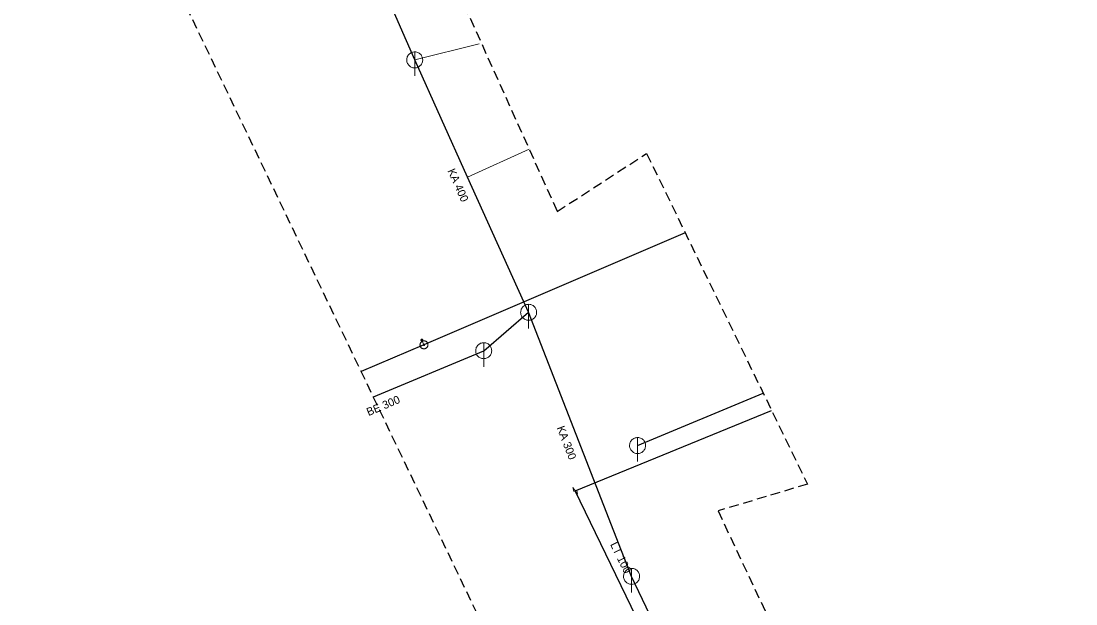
# Model space of a CAD drawing. Extents: x -688691 to -688449, y -974248 to -973966.
# Drawn here: x -688691.4 to -688559.6, y -974177 to -974104.2 of the extents above; entities that cross this region are included whole.
import ezdxf

# ---------------------------------------------------------------- set-up
doc = ezdxf.new("R2010")
doc.units = 0
doc.header["$LTSCALE"] = 0.4
doc.linetypes.add('MEDIUM_DASHED', pattern=[4.5, 3, -1.5])
for name, color, linetype, lineweight in [('1', 7, 'MEDIUM_DASHED', 25), ('11', 7, 'Continuous', 13), ('14', 7, 'Continuous', 25), ('17', 7, 'Continuous', 25), ('22', 7, 'Continuous', 13), ('47', 7, 'Continuous', 13), ('9', 7, 'Continuous', 13)]:
    doc.layers.add(name, color=color, linetype=linetype, lineweight=lineweight)

msp = doc.modelspace()

# ---------------------------------------------------------------- linework, layer by layer
at = {"layer": '1'}
msp.add_lwpolyline([(-688492.642, -974007.422), (-688474.778, -973965.553), (-688449.099, -973975.602), (-688472.545, -974030.309), (-688492.642, -974033.659), (-688555.165, -974021.936), (-688650.066, -974071.061), (-688624.387, -974128.002), (-688613.222, -974120.745), (-688593.125, -974162.055), (-688604.29, -974165.404), (-688581.96, -974212.855), (-688565.213, -974206.156), (-688558.514, -974230.719), (-688607.64, -974248.024), (-688622.154, -974231.277), (-688607.64, -974225.136), (-688626.62, -974194.433), (-688691.376, -974059.338), (-688565.213, -973995.698), (-688544, -974002.397)], close=True, dxfattribs=at)
at = {"layer": '11'}
for p, q in [((-688634.145, -974107.05), (-688642.199, -974109.067)), ((-688627.9, -974120.212), (-688635.58, -974123.722))]:
    msp.add_line(p, q, dxfattribs=at)
at = {"layer": '14'}
for p, q in [((-688642.199, -974109.067), (-688647.127, -974097.744)), ((-688633.579, -974145.386), (-688627.959, -974140.596)), ((-688647.359, -974151.167), (-688633.579, -974145.386)), ((-688614.35, -974157.235), (-688598.649, -974150.701))]:
    msp.add_line(p, q, dxfattribs=at)
at = {"layer": '14', "lineweight": 13}
msp.add_line((-688641.288, -974144.068), (-688641.038, -974144.657), dxfattribs=at)
at = {"layer": '14'}
for points in [[(-688627.959, -974140.596), (-688635.58, -974123.722), (-688642.199, -974109.067)], [(-688600.487, -974203.944), (-688609.114, -974186.109), (-688615.099, -974173.573), (-688627.959, -974140.596)]]:
    msp.add_lwpolyline(points, dxfattribs=at)
at = {"layer": '17'}
for p, q in [((-688608.391, -974130.675), (-688641.038, -974144.657)), ((-688641.038, -974144.657), (-688648.882, -974147.989)), ((-688622.145, -974162.896), (-688597.607, -974152.842)), ((-688612.61, -974182.51), (-688622.145, -974162.896))]:
    msp.add_line(p, q, dxfattribs=at)
at = {"layer": '22'}
for p, q in [((-688642.199, -974111.067), (-688642.198, -974108.067)), ((-688627.959, -974142.596), (-688627.958, -974139.596)), ((-688633.579, -974147.386), (-688633.578, -974144.386)), ((-688614.35, -974159.235), (-688614.349, -974156.235)), ((-688615.099, -974175.573), (-688615.098, -974172.573))]:
    msp.add_line(p, q, dxfattribs=at)
for points in [[(-688641.199, -974109.067), (-688641.204, -974108.958), (-688641.222, -974108.85), (-688641.252, -974108.744), (-688641.292, -974108.643), (-688641.344, -974108.546), (-688641.406, -974108.456), (-688641.478, -974108.373), (-688641.558, -974108.299), (-688641.646, -974108.233), (-688641.74, -974108.178), (-688641.84, -974108.133), (-688641.945, -974108.1), (-688642.052, -974108.078), (-688642.161, -974108.068), (-688642.271, -974108.07), (-688642.379, -974108.084), (-688642.486, -974108.109), (-688642.589, -974108.146), (-688642.687, -974108.195), (-688642.779, -974108.253), (-688642.865, -974108.322), (-688642.942, -974108.399), (-688643.011, -974108.485), (-688643.07, -974108.577), (-688643.118, -974108.675), (-688643.155, -974108.778), (-688643.181, -974108.885), (-688643.195, -974108.993), (-688643.198, -974109.103), (-688643.188, -974109.212), (-688643.167, -974109.319), (-688643.133, -974109.423), (-688643.089, -974109.523), (-688643.034, -974109.618), (-688642.968, -974109.706), (-688642.894, -974109.786), (-688642.811, -974109.858), (-688642.721, -974109.92), (-688642.625, -974109.972), (-688642.523, -974110.013), (-688642.418, -974110.043), (-688642.31, -974110.061), (-688642.2, -974110.067), (-688642.091, -974110.061), (-688641.983, -974110.043), (-688641.878, -974110.014), (-688641.776, -974109.973), (-688641.679, -974109.921), (-688641.589, -974109.859), (-688641.506, -974109.788), (-688641.431, -974109.708), (-688641.366, -974109.62), (-688641.31, -974109.526), (-688641.266, -974109.426), (-688641.232, -974109.322), (-688641.21, -974109.214), (-688641.2, -974109.105)], [(-688626.959, -974140.596), (-688626.964, -974140.487), (-688626.982, -974140.379), (-688627.012, -974140.273), (-688627.052, -974140.172), (-688627.104, -974140.075), (-688627.166, -974139.985), (-688627.238, -974139.902), (-688627.318, -974139.828), (-688627.406, -974139.762), (-688627.5, -974139.707), (-688627.6, -974139.662), (-688627.705, -974139.629), (-688627.812, -974139.607), (-688627.921, -974139.597), (-688628.031, -974139.599), (-688628.139, -974139.613), (-688628.246, -974139.638), (-688628.349, -974139.675), (-688628.447, -974139.724), (-688628.539, -974139.782), (-688628.625, -974139.851), (-688628.702, -974139.928), (-688628.771, -974140.014), (-688628.83, -974140.106), (-688628.878, -974140.204), (-688628.915, -974140.307), (-688628.941, -974140.414), (-688628.955, -974140.522), (-688628.958, -974140.632), (-688628.948, -974140.741), (-688628.927, -974140.848), (-688628.893, -974140.952), (-688628.849, -974141.052), (-688628.794, -974141.147), (-688628.728, -974141.235), (-688628.654, -974141.315), (-688628.571, -974141.387), (-688628.481, -974141.449), (-688628.385, -974141.501), (-688628.283, -974141.542), (-688628.178, -974141.572), (-688628.07, -974141.59), (-688627.96, -974141.596), (-688627.851, -974141.59), (-688627.743, -974141.572), (-688627.638, -974141.543), (-688627.536, -974141.502), (-688627.439, -974141.45), (-688627.349, -974141.388), (-688627.266, -974141.317), (-688627.191, -974141.237), (-688627.126, -974141.149), (-688627.07, -974141.055), (-688627.026, -974140.955), (-688626.992, -974140.851), (-688626.97, -974140.743), (-688626.96, -974140.634)], [(-688632.579, -974145.386), (-688632.584, -974145.277), (-688632.602, -974145.169), (-688632.632, -974145.063), (-688632.672, -974144.962), (-688632.724, -974144.865), (-688632.786, -974144.775), (-688632.858, -974144.692), (-688632.938, -974144.618), (-688633.026, -974144.552), (-688633.12, -974144.497), (-688633.22, -974144.452), (-688633.325, -974144.419), (-688633.432, -974144.397), (-688633.541, -974144.387), (-688633.651, -974144.389), (-688633.759, -974144.403), (-688633.866, -974144.428), (-688633.969, -974144.465), (-688634.067, -974144.514), (-688634.159, -974144.572), (-688634.245, -974144.641), (-688634.322, -974144.718), (-688634.391, -974144.804), (-688634.45, -974144.896), (-688634.498, -974144.994), (-688634.535, -974145.097), (-688634.561, -974145.204), (-688634.575, -974145.312), (-688634.578, -974145.422), (-688634.568, -974145.531), (-688634.547, -974145.638), (-688634.513, -974145.742), (-688634.469, -974145.842), (-688634.414, -974145.937), (-688634.348, -974146.025), (-688634.274, -974146.105), (-688634.191, -974146.177), (-688634.101, -974146.239), (-688634.005, -974146.291), (-688633.903, -974146.332), (-688633.798, -974146.362), (-688633.69, -974146.38), (-688633.58, -974146.386), (-688633.471, -974146.38), (-688633.363, -974146.362), (-688633.258, -974146.333), (-688633.156, -974146.292), (-688633.059, -974146.24), (-688632.969, -974146.178), (-688632.886, -974146.107), (-688632.811, -974146.027), (-688632.746, -974145.939), (-688632.69, -974145.845), (-688632.646, -974145.745), (-688632.612, -974145.641), (-688632.59, -974145.533), (-688632.58, -974145.424)], [(-688613.35, -974157.235), (-688613.355, -974157.126), (-688613.373, -974157.018), (-688613.403, -974156.912), (-688613.443, -974156.811), (-688613.495, -974156.714), (-688613.557, -974156.624), (-688613.629, -974156.541), (-688613.709, -974156.467), (-688613.797, -974156.401), (-688613.891, -974156.346), (-688613.991, -974156.301), (-688614.096, -974156.268), (-688614.203, -974156.246), (-688614.312, -974156.236), (-688614.422, -974156.238), (-688614.53, -974156.252), (-688614.637, -974156.277), (-688614.74, -974156.314), (-688614.838, -974156.363), (-688614.93, -974156.421), (-688615.016, -974156.49), (-688615.093, -974156.567), (-688615.162, -974156.653), (-688615.221, -974156.745), (-688615.269, -974156.843), (-688615.306, -974156.946), (-688615.332, -974157.053), (-688615.346, -974157.161), (-688615.349, -974157.271), (-688615.339, -974157.38), (-688615.318, -974157.487), (-688615.284, -974157.591), (-688615.24, -974157.691), (-688615.185, -974157.786), (-688615.119, -974157.874), (-688615.045, -974157.954), (-688614.962, -974158.026), (-688614.872, -974158.088), (-688614.776, -974158.14), (-688614.674, -974158.181), (-688614.569, -974158.211), (-688614.461, -974158.229), (-688614.351, -974158.235), (-688614.242, -974158.229), (-688614.134, -974158.211), (-688614.029, -974158.182), (-688613.927, -974158.141), (-688613.83, -974158.089), (-688613.74, -974158.027), (-688613.657, -974157.956), (-688613.582, -974157.876), (-688613.517, -974157.788), (-688613.461, -974157.694), (-688613.417, -974157.594), (-688613.383, -974157.49), (-688613.361, -974157.382), (-688613.351, -974157.273)], [(-688614.099, -974173.573), (-688614.104, -974173.464), (-688614.122, -974173.356), (-688614.152, -974173.25), (-688614.192, -974173.149), (-688614.244, -974173.052), (-688614.306, -974172.962), (-688614.378, -974172.879), (-688614.458, -974172.805), (-688614.546, -974172.739), (-688614.64, -974172.684), (-688614.74, -974172.639), (-688614.845, -974172.606), (-688614.952, -974172.584), (-688615.061, -974172.574), (-688615.171, -974172.576), (-688615.279, -974172.59), (-688615.386, -974172.615), (-688615.489, -974172.652), (-688615.587, -974172.701), (-688615.679, -974172.759), (-688615.765, -974172.828), (-688615.842, -974172.905), (-688615.911, -974172.991), (-688615.97, -974173.083), (-688616.018, -974173.181), (-688616.055, -974173.284), (-688616.081, -974173.391), (-688616.095, -974173.499), (-688616.098, -974173.609), (-688616.088, -974173.718), (-688616.067, -974173.825), (-688616.033, -974173.929), (-688615.989, -974174.029), (-688615.934, -974174.124), (-688615.868, -974174.212), (-688615.794, -974174.292), (-688615.711, -974174.364), (-688615.621, -974174.426), (-688615.525, -974174.478), (-688615.423, -974174.519), (-688615.318, -974174.549), (-688615.21, -974174.567), (-688615.1, -974174.573), (-688614.991, -974174.567), (-688614.883, -974174.549), (-688614.778, -974174.52), (-688614.676, -974174.479), (-688614.579, -974174.427), (-688614.489, -974174.365), (-688614.406, -974174.294), (-688614.331, -974174.214), (-688614.266, -974174.126), (-688614.21, -974174.032), (-688614.166, -974173.932), (-688614.132, -974173.828), (-688614.11, -974173.72), (-688614.1, -974173.611)]]:
    msp.add_lwpolyline(points, close=True, dxfattribs=at)
at = {"layer": '47'}
msp.add_line((-688622.424, -974162.47), (-688622.331, -974162.971), dxfattribs=at)
for points in [[(-688640.577, -974144.461), (-688640.601, -974144.414), (-688640.628, -974144.369), (-688640.661, -974144.329), (-688640.696, -974144.291), (-688640.737, -974144.257), (-688640.781, -974144.228), (-688640.827, -974144.204), (-688640.875, -974144.184), (-688640.925, -974144.17), (-688640.977, -974144.16), (-688641.03, -974144.157), (-688641.082, -974144.159), (-688641.133, -974144.166), (-688641.184, -974144.179), (-688641.233, -974144.196), (-688641.28, -974144.22), (-688641.325, -974144.247), (-688641.366, -974144.28), (-688641.403, -974144.315), (-688641.437, -974144.356), (-688641.466, -974144.4), (-688641.491, -974144.446), (-688641.511, -974144.495), (-688641.525, -974144.545), (-688641.534, -974144.596), (-688641.537, -974144.649), (-688641.536, -974144.701), (-688641.528, -974144.752), (-688641.515, -974144.803), (-688641.498, -974144.852), (-688641.474, -974144.899), (-688641.447, -974144.944), (-688641.415, -974144.986), (-688641.379, -974145.022), (-688641.338, -974145.056), (-688641.295, -974145.086), (-688641.249, -974145.11), (-688641.2, -974145.13), (-688641.149, -974145.144), (-688641.098, -974145.153), (-688641.045, -974145.156), (-688640.994, -974145.155), (-688640.942, -974145.147), (-688640.891, -974145.134), (-688640.842, -974145.117), (-688640.795, -974145.093), (-688640.75, -974145.066), (-688640.709, -974145.034), (-688640.672, -974144.998), (-688640.638, -974144.957), (-688640.608, -974144.914), (-688640.585, -974144.868), (-688640.565, -974144.819), (-688640.551, -974144.769), (-688640.541, -974144.717), (-688640.538, -974144.664), (-688640.54, -974144.613), (-688640.547, -974144.561), (-688640.56, -974144.51)], [(-688640.962, -974144.624), (-688640.966, -974144.616), (-688640.971, -974144.61), (-688640.976, -974144.603), (-688640.981, -974144.597), (-688640.988, -974144.591), (-688640.996, -974144.586), (-688641.003, -974144.582), (-688641.011, -974144.579), (-688641.019, -974144.577), (-688641.028, -974144.575), (-688641.037, -974144.575), (-688641.045, -974144.575), (-688641.053, -974144.576), (-688641.061, -974144.578), (-688641.07, -974144.581), (-688641.078, -974144.585), (-688641.084, -974144.59), (-688641.091, -974144.595), (-688641.097, -974144.6), (-688641.103, -974144.607), (-688641.108, -974144.615), (-688641.112, -974144.622), (-688641.115, -974144.63), (-688641.118, -974144.639), (-688641.119, -974144.647), (-688641.119, -974144.656), (-688641.119, -974144.664), (-688641.118, -974144.672), (-688641.116, -974144.68), (-688641.113, -974144.689), (-688641.109, -974144.697), (-688641.104, -974144.703), (-688641.099, -974144.71), (-688641.094, -974144.716), (-688641.087, -974144.722), (-688641.08, -974144.727), (-688641.072, -974144.731), (-688641.064, -974144.734), (-688641.055, -974144.737), (-688641.047, -974144.738), (-688641.038, -974144.738), (-688641.03, -974144.738), (-688641.022, -974144.737), (-688641.014, -974144.735), (-688641.005, -974144.732), (-688640.997, -974144.728), (-688640.991, -974144.723), (-688640.984, -974144.718), (-688640.978, -974144.713), (-688640.972, -974144.706), (-688640.967, -974144.699), (-688640.963, -974144.691), (-688640.96, -974144.683), (-688640.958, -974144.675), (-688640.956, -974144.666), (-688640.956, -974144.657), (-688640.956, -974144.649), (-688640.957, -974144.641), (-688640.959, -974144.633)]]:
    msp.add_lwpolyline(points, close=True, dxfattribs=at)
msp.add_lwpolyline([(-688622.424, -974162.47), (-688621.865, -974163.321), (-688621.958, -974162.82)], dxfattribs=at)
at = {"layer": '9'}
for points in [[(-688641.414, -974144.068), (-688641.414, -974144.081), (-688641.411, -974144.094), (-688641.409, -974144.107), (-688641.404, -974144.119), (-688641.397, -974144.131), (-688641.391, -974144.142), (-688641.382, -974144.152), (-688641.372, -974144.162), (-688641.362, -974144.17), (-688641.352, -974144.177), (-688641.34, -974144.183), (-688641.328, -974144.188), (-688641.315, -974144.191), (-688641.301, -974144.193), (-688641.289, -974144.195), (-688641.276, -974144.194), (-688641.262, -974144.192), (-688641.25, -974144.189), (-688641.237, -974144.184), (-688641.225, -974144.178), (-688641.215, -974144.171), (-688641.205, -974144.163), (-688641.195, -974144.153), (-688641.186, -974144.143), (-688641.179, -974144.132), (-688641.174, -974144.12), (-688641.169, -974144.108), (-688641.166, -974144.095), (-688641.164, -974144.082), (-688641.161, -974144.069), (-688641.163, -974144.056), (-688641.164, -974144.043), (-688641.168, -974144.03), (-688641.173, -974144.018), (-688641.178, -974144.006), (-688641.186, -974143.995), (-688641.193, -974143.985), (-688641.203, -974143.975), (-688641.213, -974143.967), (-688641.225, -974143.96), (-688641.237, -974143.954), (-688641.249, -974143.949), (-688641.262, -974143.946), (-688641.274, -974143.944), (-688641.288, -974143.943), (-688641.301, -974143.943), (-688641.313, -974143.945), (-688641.326, -974143.948), (-688641.338, -974143.953), (-688641.35, -974143.959), (-688641.362, -974143.966), (-688641.372, -974143.974), (-688641.382, -974143.984), (-688641.389, -974143.994), (-688641.397, -974144.005), (-688641.402, -974144.017), (-688641.407, -974144.029), (-688641.411, -974144.042), (-688641.413, -974144.055)], [(-688641.394, -974144.068), (-688641.394, -974144.079), (-688641.392, -974144.09), (-688641.389, -974144.101), (-688641.386, -974144.111), (-688641.38, -974144.121), (-688641.375, -974144.13), (-688641.367, -974144.139), (-688641.36, -974144.147), (-688641.35, -974144.154), (-688641.342, -974144.16), (-688641.331, -974144.165), (-688641.321, -974144.169), (-688641.311, -974144.172), (-688641.299, -974144.175), (-688641.289, -974144.175), (-688641.277, -974144.175), (-688641.267, -974144.173), (-688641.255, -974144.17), (-688641.245, -974144.166), (-688641.235, -974144.161), (-688641.227, -974144.155), (-688641.218, -974144.148), (-688641.21, -974144.14), (-688641.203, -974144.131), (-688641.196, -974144.122), (-688641.191, -974144.112), (-688641.188, -974144.102), (-688641.184, -974144.091), (-688641.183, -974144.08), (-688641.181, -974144.069), (-688641.181, -974144.058), (-688641.183, -974144.047), (-688641.186, -974144.036), (-688641.191, -974144.026), (-688641.196, -974144.016), (-688641.201, -974144.007), (-688641.208, -974143.998), (-688641.217, -974143.99), (-688641.225, -974143.983), (-688641.235, -974143.977), (-688641.245, -974143.972), (-688641.254, -974143.968), (-688641.266, -974143.965), (-688641.276, -974143.963), (-688641.288, -974143.963), (-688641.299, -974143.962), (-688641.309, -974143.964), (-688641.321, -974143.967), (-688641.33, -974143.971), (-688641.34, -974143.976), (-688641.35, -974143.982), (-688641.358, -974143.989), (-688641.367, -974143.997), (-688641.374, -974144.006), (-688641.379, -974144.015), (-688641.384, -974144.025), (-688641.389, -974144.035), (-688641.392, -974144.046), (-688641.394, -974144.057)], [(-688641.375, -974144.068), (-688641.375, -974144.077), (-688641.374, -974144.086), (-688641.37, -974144.095), (-688641.367, -974144.103), (-688641.364, -974144.111), (-688641.358, -974144.119), (-688641.352, -974144.126), (-688641.347, -974144.132), (-688641.34, -974144.138), (-688641.331, -974144.143), (-688641.323, -974144.147), (-688641.316, -974144.15), (-688641.306, -974144.153), (-688641.298, -974144.154), (-688641.289, -974144.156), (-688641.279, -974144.155), (-688641.271, -974144.154), (-688641.262, -974144.151), (-688641.254, -974144.148), (-688641.245, -974144.144), (-688641.237, -974144.139), (-688641.23, -974144.133), (-688641.225, -974144.127), (-688641.218, -974144.12), (-688641.213, -974144.112), (-688641.21, -974144.104), (-688641.206, -974144.096), (-688641.203, -974144.087), (-688641.203, -974144.078), (-688641.2, -974144.069), (-688641.201, -974144.06), (-688641.203, -974144.051), (-688641.205, -974144.042), (-688641.208, -974144.034), (-688641.213, -974144.026), (-688641.218, -974144.018), (-688641.223, -974144.011), (-688641.23, -974144.005), (-688641.237, -974143.999), (-688641.245, -974143.994), (-688641.252, -974143.99), (-688641.261, -974143.987), (-688641.269, -974143.984), (-688641.279, -974143.983), (-688641.288, -974143.982), (-688641.296, -974143.982), (-688641.306, -974143.983), (-688641.315, -974143.986), (-688641.323, -974143.989), (-688641.33, -974143.993), (-688641.338, -974143.998), (-688641.345, -974144.004), (-688641.352, -974144.01), (-688641.357, -974144.017), (-688641.362, -974144.025), (-688641.367, -974144.033), (-688641.37, -974144.041), (-688641.372, -974144.05), (-688641.374, -974144.059)], [(-688641.355, -974144.068), (-688641.355, -974144.075), (-688641.353, -974144.082), (-688641.352, -974144.089), (-688641.35, -974144.095), (-688641.347, -974144.101), (-688641.343, -974144.107), (-688641.338, -974144.113), (-688641.333, -974144.118), (-688641.328, -974144.122), (-688641.321, -974144.126), (-688641.316, -974144.129), (-688641.309, -974144.132), (-688641.303, -974144.133), (-688641.296, -974144.136), (-688641.289, -974144.136), (-688641.281, -974144.136), (-688641.274, -974144.134), (-688641.267, -974144.133), (-688641.262, -974144.13), (-688641.254, -974144.127), (-688641.25, -974144.123), (-688641.244, -974144.119), (-688641.239, -974144.114), (-688641.235, -974144.108), (-688641.23, -974144.102), (-688641.227, -974144.096), (-688641.225, -974144.09), (-688641.223, -974144.083), (-688641.222, -974144.076), (-688641.22, -974144.069), (-688641.22, -974144.062), (-688641.222, -974144.055), (-688641.223, -974144.048), (-688641.227, -974144.042), (-688641.23, -974144.035), (-688641.233, -974144.03), (-688641.237, -974144.024), (-688641.242, -974144.019), (-688641.249, -974144.015), (-688641.254, -974144.011), (-688641.261, -974144.008), (-688641.267, -974144.005), (-688641.274, -974144.003), (-688641.281, -974144.002), (-688641.288, -974144.002), (-688641.294, -974144.002), (-688641.301, -974144.002), (-688641.308, -974144.004), (-688641.315, -974144.007), (-688641.321, -974144.01), (-688641.326, -974144.014), (-688641.333, -974144.018), (-688641.338, -974144.023), (-688641.342, -974144.029), (-688641.345, -974144.034), (-688641.348, -974144.041), (-688641.352, -974144.047), (-688641.352, -974144.054), (-688641.355, -974144.061)], [(-688641.335, -974144.068), (-688641.335, -974144.073), (-688641.335, -974144.078), (-688641.333, -974144.083), (-688641.331, -974144.087), (-688641.33, -974144.092), (-688641.326, -974144.096), (-688641.323, -974144.099), (-688641.32, -974144.103), (-688641.316, -974144.106), (-688641.313, -974144.109), (-688641.308, -974144.111), (-688641.303, -974144.113), (-688641.299, -974144.114), (-688641.294, -974144.116), (-688641.289, -974144.116), (-688641.284, -974144.116), (-688641.279, -974144.115), (-688641.274, -974144.114), (-688641.269, -974144.112), (-688641.264, -974144.11), (-688641.261, -974144.107), (-688641.257, -974144.104), (-688641.254, -974144.1), (-688641.25, -974144.097), (-688641.247, -974144.093), (-688641.245, -974144.088), (-688641.244, -974144.084), (-688641.242, -974144.079), (-688641.242, -974144.074), (-688641.24, -974144.069), (-688641.24, -974144.064), (-688641.242, -974144.059), (-688641.242, -974144.054), (-688641.245, -974144.05), (-688641.247, -974144.045), (-688641.25, -974144.041), (-688641.252, -974144.037), (-688641.255, -974144.034), (-688641.259, -974144.031), (-688641.264, -974144.028), (-688641.269, -974144.026), (-688641.272, -974144.024), (-688641.277, -974144.023), (-688641.282, -974144.022), (-688641.288, -974144.022), (-688641.293, -974144.022), (-688641.298, -974144.023), (-688641.303, -974144.023), (-688641.306, -974144.025), (-688641.311, -974144.027), (-688641.316, -974144.03), (-688641.318, -974144.033), (-688641.323, -974144.036), (-688641.325, -974144.04), (-688641.328, -974144.044), (-688641.33, -974144.049), (-688641.333, -974144.053), (-688641.333, -974144.058), (-688641.335, -974144.063)], [(-688641.315, -974144.068), (-688641.315, -974144.071), (-688641.316, -974144.074), (-688641.315, -974144.076), (-688641.313, -974144.079), (-688641.313, -974144.082), (-688641.311, -974144.084), (-688641.308, -974144.086), (-688641.306, -974144.088), (-688641.304, -974144.09), (-688641.303, -974144.092), (-688641.299, -974144.094), (-688641.296, -974144.095), (-688641.294, -974144.095), (-688641.291, -974144.096), (-688641.289, -974144.096), (-688641.286, -974144.096), (-688641.282, -974144.096), (-688641.279, -974144.095), (-688641.277, -974144.094), (-688641.274, -974144.093), (-688641.272, -974144.091), (-688641.269, -974144.089), (-688641.267, -974144.087), (-688641.267, -974144.085), (-688641.264, -974144.083), (-688641.264, -974144.08), (-688641.262, -974144.077), (-688641.262, -974144.075), (-688641.261, -974144.072), (-688641.259, -974144.069), (-688641.261, -974144.066), (-688641.261, -974144.063), (-688641.262, -974144.06), (-688641.262, -974144.058), (-688641.264, -974144.055), (-688641.266, -974144.053), (-688641.267, -974144.05), (-688641.269, -974144.048), (-688641.272, -974144.047), (-688641.274, -974144.045), (-688641.276, -974144.044), (-688641.279, -974144.043), (-688641.281, -974144.042), (-688641.284, -974144.042), (-688641.288, -974144.041), (-688641.291, -974144.042), (-688641.294, -974144.041), (-688641.296, -974144.043), (-688641.299, -974144.043), (-688641.301, -974144.044), (-688641.303, -974144.046), (-688641.306, -974144.047), (-688641.308, -974144.049), (-688641.309, -974144.052), (-688641.311, -974144.054), (-688641.313, -974144.057), (-688641.313, -974144.059), (-688641.315, -974144.062), (-688641.315, -974144.065)], [(-688641.296, -974144.068), (-688641.296, -974144.07), (-688641.296, -974144.07), (-688641.294, -974144.07), (-688641.294, -974144.072), (-688641.296, -974144.073), (-688641.294, -974144.073), (-688641.294, -974144.073), (-688641.294, -974144.075), (-688641.294, -974144.075), (-688641.293, -974144.076), (-688641.291, -974144.076), (-688641.291, -974144.076), (-688641.291, -974144.077), (-688641.289, -974144.077), (-688641.289, -974144.077), (-688641.288, -974144.077), (-688641.286, -974144.077), (-688641.286, -974144.076), (-688641.286, -974144.076), (-688641.284, -974144.076), (-688641.284, -974144.075), (-688641.284, -974144.075), (-688641.282, -974144.074), (-688641.282, -974144.074), (-688641.281, -974144.073), (-688641.281, -974144.072), (-688641.279, -974144.071), (-688641.279, -974144.071), (-688641.279, -974144.07), (-688641.279, -974144.069), (-688641.279, -974144.068), (-688641.279, -974144.067), (-688641.279, -974144.067), (-688641.281, -974144.066), (-688641.281, -974144.065), (-688641.281, -974144.064), (-688641.281, -974144.064), (-688641.282, -974144.063), (-688641.282, -974144.063), (-688641.284, -974144.062), (-688641.284, -974144.062), (-688641.286, -974144.061), (-688641.286, -974144.061), (-688641.286, -974144.061), (-688641.288, -974144.061), (-688641.289, -974144.061), (-688641.289, -974144.061), (-688641.289, -974144.061), (-688641.291, -974144.062), (-688641.291, -974144.061), (-688641.293, -974144.063), (-688641.293, -974144.063), (-688641.294, -974144.063), (-688641.294, -974144.063), (-688641.294, -974144.065), (-688641.294, -974144.066), (-688641.294, -974144.067), (-688641.296, -974144.067), (-688641.296, -974144.068)]]:
    msp.add_lwpolyline(points, close=True, dxfattribs=at)

# ---------------------------------------------------------------- texts
at = {"layer": '1'}
for s, rotation, p in [('KA 400', 294, (-688638.123, -974122.914)), ('BE 300', 23, (-688647.96, -974153.566)), ('KA 300', 291, (-688624.468, -974155.01)), ('LT 100', 296, (-688617.802, -974169.574))]:
    msp.add_text(s, height=1, rotation=rotation, dxfattribs=at).set_placement(p)

doc.saveas('drawing.dxf')
